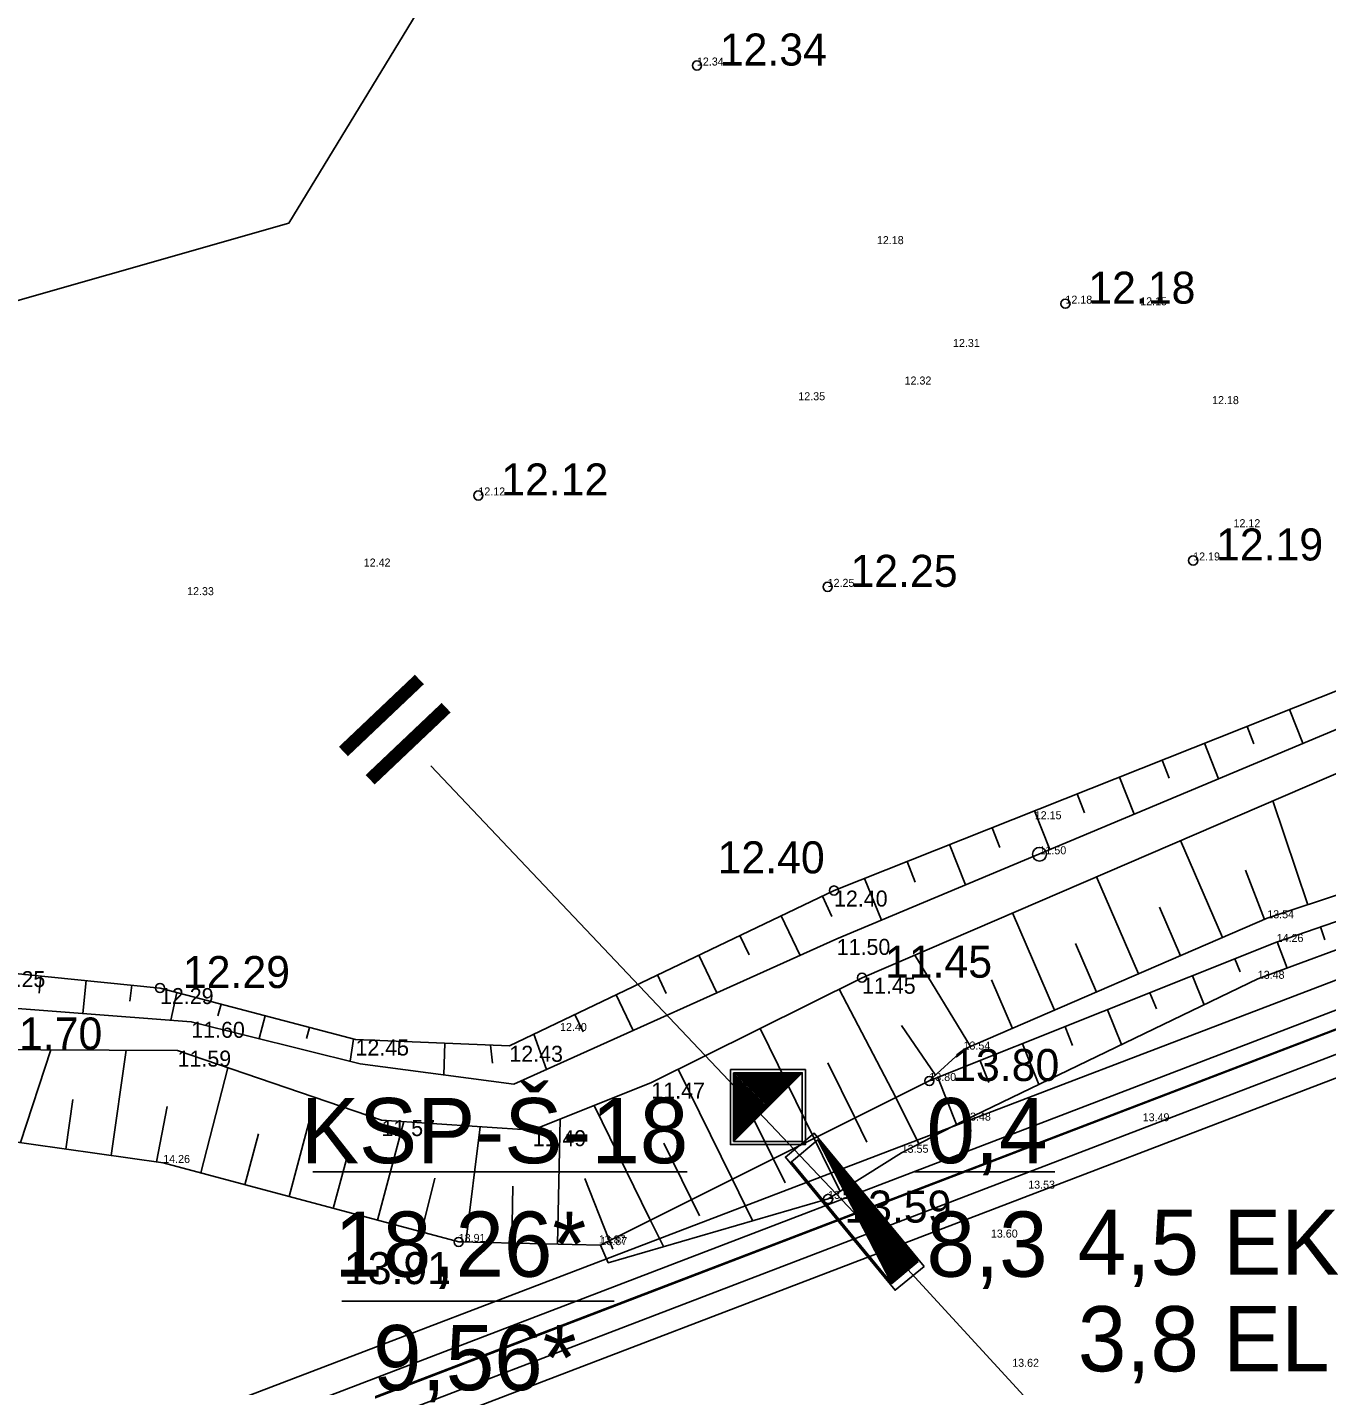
# Model space of a CAD drawing. Extents: x 433497 to 434382, y 6534486 to 6534993.
# Drawn here: x 433616.2 to 433673.1, y 6534797 to 6534856.4 of the extents above; entities that cross this region are included whole.
import ezdxf

# ---------------------------------------------------------------- set-up
doc = ezdxf.new("R2010")
doc.units = 0
for name, color, linetype in [('Default', 7, 'Continuous'), ('GEOLPUNKT', 7, 'Continuous'), ('kataster', 7, 'Continuous'), ('KORGUS-EH2000', 7, 'Continuous'), ('l__x00e4__bil__x00f5__iked', 7, 'Continuous'), ('MOOTKORG-EH2000', 7, 'Continuous'), ('PIIR', 7, 'Continuous'), ('RELJEEF', 7, 'Continuous'), ('VEEKOGU', 7, 'Continuous'), ('VORMISTUS', 7, 'Continuous')]:
    doc.layers.add(name, color=color, linetype=linetype)

msp = doc.modelspace()

# ---------------------------------------------------------------- linework, layer by layer
at = {"layer": 'Default'}
msp.add_lwpolyline([(433617.12, 6534791.025), (433632.75, 6534606.045), (434137.38, 6534796.515), (434127.69, 6534855.6), (433968.21, 6534911.925), (433942.38, 6534904.035), (433920.99, 6534907.275)], close=True, dxfattribs=at)
msp.add_lwpolyline([(433617.12, 6534791.025), (433632.75, 6534606.045), (434137.38, 6534796.515), (434127.69, 6534855.6), (433968.21, 6534911.925), (433942.38, 6534904.035), (433920.99, 6534907.275)], close=True, dxfattribs=at)
msp.add_lwpolyline([(433617.12, 6534791.025), (433632.75, 6534606.045), (434137.38, 6534796.515), (434127.69, 6534855.6), (433968.21, 6534911.925), (433942.38, 6534904.035), (433920.99, 6534907.275)], close=True, dxfattribs=at)
at = {"layer": 'GEOLPUNKT'}
for p, q in [((433647.136, 6534807.67), (433650.136, 6534810.67)), ((433647.136, 6534807.7), (433650.106, 6534810.67)), ((433647.136, 6534807.771), (433650.035, 6534810.67)), ((433647.136, 6534807.842), (433649.965, 6534810.67)), ((433647.136, 6534807.912), (433649.894, 6534810.67)), ((433647.136, 6534807.983), (433649.823, 6534810.67)), ((433647.136, 6534808.054), (433649.752, 6534810.67)), ((433647.136, 6534808.124), (433649.682, 6534810.67)), ((433647.136, 6534808.195), (433649.611, 6534810.67)), ((433647.136, 6534808.266), (433649.54, 6534810.67)), ((433647.136, 6534808.337), (433649.47, 6534810.67)), ((433647.136, 6534808.407), (433649.399, 6534810.67)), ((433647.136, 6534808.478), (433649.328, 6534810.67)), ((433647.136, 6534808.549), (433649.257, 6534810.67)), ((433647.136, 6534808.619), (433649.187, 6534810.67)), ((433647.136, 6534808.69), (433649.116, 6534810.67)), ((433647.136, 6534808.761), (433649.045, 6534810.67)), ((433647.136, 6534808.832), (433648.975, 6534810.67)), ((433647.136, 6534808.902), (433648.904, 6534810.67)), ((433647.136, 6534808.973), (433648.833, 6534810.67)), ((433647.136, 6534809.044), (433648.763, 6534810.67)), ((433647.136, 6534809.114), (433648.692, 6534810.67)), ((433647.136, 6534809.185), (433648.621, 6534810.67)), ((433647.136, 6534809.256), (433648.55, 6534810.67)), ((433647.136, 6534809.327), (433648.48, 6534810.67)), ((433647.136, 6534809.397), (433648.409, 6534810.67)), ((433647.136, 6534809.468), (433648.338, 6534810.67)), ((433647.136, 6534809.539), (433648.268, 6534810.67)), ((433647.136, 6534809.609), (433648.197, 6534810.67)), ((433647.136, 6534809.68), (433648.126, 6534810.67)), ((433647.136, 6534809.751), (433648.055, 6534810.67)), ((433647.136, 6534809.822), (433647.985, 6534810.67)), ((433647.136, 6534809.892), (433647.914, 6534810.67)), ((433647.136, 6534809.963), (433647.843, 6534810.67)), ((433647.136, 6534810.034), (433647.773, 6534810.67)), ((433647.136, 6534810.104), (433647.702, 6534810.67)), ((433647.136, 6534810.175), (433647.631, 6534810.67)), ((433647.136, 6534810.246), (433647.56, 6534810.67)), ((433647.136, 6534810.317), (433647.49, 6534810.67)), ((433647.136, 6534810.387), (433647.419, 6534810.67)), ((433647.136, 6534810.458), (433647.348, 6534810.67)), ((433647.136, 6534810.529), (433647.278, 6534810.67)), ((433647.136, 6534810.599), (433647.207, 6534810.67)), ((433648.636, 6534809.17), (433648.636, 6534809.17)), ((433650.818, 6534807.733), (433654.049, 6534801.455)), ((433650.863, 6534807.679), (433654.061, 6534801.465)), ((433650.966, 6534807.554), (433654.088, 6534801.487)), ((433651.069, 6534807.428), (433654.115, 6534801.51)), ((433651.173, 6534807.303), (433654.143, 6534801.532)), ((433651.276, 6534807.177), (433654.17, 6534801.555)), ((433651.38, 6534807.052), (433654.197, 6534801.577)), ((433651.483, 6534806.926), (433654.225, 6534801.6)), ((433651.587, 6534806.801), (433654.252, 6534801.622)), ((433651.69, 6534806.675), (433654.279, 6534801.645)), ((433651.794, 6534806.55), (433654.306, 6534801.667)), ((433651.897, 6534806.424), (433654.334, 6534801.69)), ((433652, 6534806.299), (433654.361, 6534801.712)), ((433652.104, 6534806.173), (433654.388, 6534801.734)), ((433652.207, 6534806.048), (433654.416, 6534801.757)), ((433652.311, 6534805.922), (433654.443, 6534801.779)), ((433652.414, 6534805.797), (433654.47, 6534801.802)), ((433652.518, 6534805.671), (433654.497, 6534801.824)), ((433652.621, 6534805.546), (433654.525, 6534801.847)), ((433652.724, 6534805.42), (433654.552, 6534801.869)), ((433652.828, 6534805.295), (433654.579, 6534801.892)), ((433652.931, 6534805.169), (433654.607, 6534801.914)), ((433653.035, 6534805.044), (433654.634, 6534801.937)), ((433653.138, 6534804.918), (433654.661, 6534801.959)), ((433653.242, 6534804.793), (433654.688, 6534801.982)), ((433653.345, 6534804.667), (433654.716, 6534802.004)), ((433653.449, 6534804.542), (433654.743, 6534802.027)), ((433653.552, 6534804.416), (433654.77, 6534802.049)), ((433653.655, 6534804.291), (433654.797, 6534802.072)), ((433653.759, 6534804.165), (433654.825, 6534802.094)), ((433653.862, 6534804.04), (433654.852, 6534802.117)), ((433653.966, 6534803.914), (433654.879, 6534802.139)), ((433654.069, 6534803.789), (433654.907, 6534802.162)), ((433654.173, 6534803.663), (433654.934, 6534802.184)), ((433654.276, 6534803.538), (433654.961, 6534802.207)), ((433654.38, 6534803.412), (433654.988, 6534802.229)), ((433654.483, 6534803.287), (433655.016, 6534802.252)), ((433654.586, 6534803.161), (433655.043, 6534802.274)), ((433654.69, 6534803.036), (433655.07, 6534802.297)), ((433654.793, 6534802.91), (433655.098, 6534802.319)), ((433654.897, 6534802.785), (433655.125, 6534802.342)), ((433655, 6534802.659), (433655.152, 6534802.364)), ((433655.104, 6534802.534), (433655.179, 6534802.387))]:
    msp.add_line(p, q, dxfattribs=at)
for points in [[(433646.995, 6534810.811), (433650.277, 6534810.811), (433650.277, 6534807.529), (433646.995, 6534807.529)], [(433647.136, 6534810.67), (433650.136, 6534810.67), (433650.136, 6534807.67), (433647.136, 6534807.67)], [(433655.467, 6534802.204), (433654.201, 6534801.16), (433649.4, 6534806.985), (433650.666, 6534808.029)], [(433655.207, 6534802.409), (433654.049, 6534801.455), (433649.66, 6534806.779), (433650.818, 6534807.733)]]:
    msp.add_lwpolyline(points, close=True, dxfattribs=at)
for points in [[(433628.724, 6534806.333), (433645.109, 6534806.333)], [(433655.06, 6534806.333), (433661.188, 6534806.333)], [(433629.995, 6534800.679), (433641.912, 6534800.679)]]:
    msp.add_lwpolyline(points, dxfattribs=at)
at = {"layer": 'kataster'}
msp.add_lwpolyline([(433617.102, 6534791.002), (433632.769, 6534606.029), (434137.446, 6534796.469), (434127.827, 6534855.589), (433950.026, 6534918.39)], close=True, dxfattribs=at)
at = {"layer": 'KORGUS-EH2000'}
for centre in [(433645.531, 6534854.725), (433661.65, 6534844.309), (433635.97, 6534835.92), (433667.238, 6534833.078), (433651.248, 6534831.924), (433651.528, 6534818.64), (433652.755, 6534814.828), (433622.045, 6534814.376), (433655.696, 6534810.311), (433651.269, 6534805.154), (433635.11, 6534803.273)]:
    msp.add_circle(centre, 0.2, dxfattribs=at)
at = {"layer": 'l__x00e4__bil__x00f5__iked'}
msp.add_lwpolyline([(433633.89, 6534824.093), (433654.744, 6534802.081), (433736.834, 6534712.709), (433742.792, 6534710.723), (433773.907, 6534661.568), (433785.989, 6534638.563)], dxfattribs=at)
at = {"layer": 'PIIR'}
for points in [[(433632.021, 6534604.835), (434138.248, 6534795.936), (434128.468, 6534856.135), (433968.226, 6534912.818), (433942.33, 6534904.85), (433920.952, 6534908.165), (433616.327, 6534791.524), (433632.021, 6534604.835)], [(433632.732, 6534605.959), (434137.353, 6534796.454), (434127.754, 6534855.539), (433968.208, 6534911.976), (433942.39, 6534904.031), (433921.04, 6534907.341), (433617.174, 6534790.992), (433632.732, 6534605.959)], [(433616.435, 6534792.923), (433775.118, 6534853.561)]]:
    msp.add_lwpolyline(points, dxfattribs=at)
for points in [[(433618.234, 6534790.327), (433921.149, 6534906.313), (433942.464, 6534903.008), (433968.187, 6534910.923), (434126.862, 6534854.794), (434136.235, 6534797.101), (433633.617, 6534607.362)], [(433619.24, 6534789.695), (433634.52, 6534608.851), (434135.141, 6534797.808), (434125.908, 6534854.108), (433968.165, 6534909.82), (433942.53, 6534901.99), (433921.212, 6534905.219)], [(433619.24, 6534789.695), (433634.52, 6534608.851), (434135.141, 6534797.808), (434125.908, 6534854.108), (433968.165, 6534909.82), (433942.53, 6534901.99), (433921.212, 6534905.219)]]:
    msp.add_lwpolyline(points, close=True, dxfattribs=at)
at = {"layer": 'RELJEEF'}
for p, q in [((433671.453, 6534826.557), (433672.039, 6534825.082)), ((433669.894, 6534825.063), (433669.594, 6534825.818)), ((433667.735, 6534825.08), (433668.349, 6534823.534)), ((433666.191, 6534823.55), (433665.877, 6534824.341)), ((433664.018, 6534823.603), (433664.66, 6534821.986)), ((433662.488, 6534822.038), (433662.159, 6534822.864)), ((433672.246, 6534818.016), (433670.722, 6534822.561)), ((433660.301, 6534822.126), (433660.971, 6534820.438)), ((433658.784, 6534820.525), (433658.442, 6534821.387)), ((433656.583, 6534820.649), (433657.282, 6534818.89)), ((433668.517, 6534816.581), (433666.683, 6534820.823)), ((433655.081, 6534819.013), (433654.725, 6534819.91)), ((433669.523, 6534819.531), (433670.353, 6534817.375)), ((433652.866, 6534819.172), (433653.61, 6534817.349)), ((433664.845, 6534814.994), (433663.009, 6534819.242)), ((433651.425, 6534817.5), (433651.022, 6534818.398)), ((433661.173, 6534813.407), (433659.335, 6534817.66)), ((433665.764, 6534817.91), (433666.681, 6534815.788)), ((433649.218, 6534817.536), (433650.046, 6534815.805)), ((433673, 6534816.492), (433672.808, 6534817.05)), ((433647.817, 6534815.829), (433647.414, 6534816.673)), ((433670.917, 6534816.399), (433671.343, 6534815.253)), ((433645.609, 6534815.81), (433646.397, 6534814.164)), ((433657.502, 6534811.82), (433655.062, 6534815.821)), ((433662.091, 6534816.326), (433663.009, 6534814.201)), ((433669.288, 6534815.087), (433669.06, 6534815.657)), ((433616.755, 6534814.158), (433616.83, 6534814.901)), ((433618.82, 6534814.701), (433618.675, 6534813.263)), ((433644.188, 6534814.145), (433643.805, 6534814.948)), ((433658.418, 6534814.742), (433659.338, 6534812.614)), ((433667.203, 6534814.914), (433667.711, 6534813.646)), ((433620.719, 6534813.807), (433620.81, 6534814.5)), ((433622.779, 6534814.183), (433622.522, 6534812.968)), ((433642, 6534814.085), (433642.748, 6534812.522)), ((433654.233, 6534809.592), (433651.749, 6534814.328)), ((433665.626, 6534813.473), (433665.346, 6534814.172)), ((433624.577, 6534813.159), (433624.713, 6534813.674)), ((433663.489, 6534813.429), (433664.1, 6534811.902)), ((433626.647, 6534813.165), (433626.383, 6534812.163)), ((433640.56, 6534812.462), (433640.196, 6534813.223)), ((433628.453, 6534812.169), (433628.581, 6534812.656)), ((433638.392, 6534812.36), (433638.95, 6534810.814)), ((433650.643, 6534807.828), (433648.294, 6534812.609)), ((433654.479, 6534812.745), (433655.968, 6534810.561)), ((433661.963, 6534811.858), (433661.632, 6534812.686)), ((433615.944, 6534807.614), (433617.266, 6534811.67)), ((433619.905, 6534807.05), (433620.559, 6534811.652)), ((433630.515, 6534812.147), (433630.365, 6534811.175)), ((433632.484, 6534811.448), (433632.511, 6534812.048)), ((433634.509, 6534811.966), (433634.453, 6534810.583)), ((433636.59, 6534811.086), (433636.508, 6534811.884)), ((433659.775, 6534811.943), (433660.489, 6534810.159)), ((433651.261, 6534811.105), (433652.438, 6534808.71)), ((433658.301, 6534810.243), (433657.918, 6534811.2)), ((433623.824, 6534806.288), (433625.009, 6534810.892)), ((433647.052, 6534806.065), (433644.713, 6534810.827)), ((433656.062, 6534810.457), (433656.882, 6534808.406)), ((433618.233, 6534809.498), (433617.925, 6534807.332)), ((433627.689, 6534805.256), (433628.845, 6534809.585)), ((433647.675, 6534809.332), (433648.847, 6534806.947)), ((433654.233, 6534809.592), (433655.233, 6534807.556)), ((433622.358, 6534809.201), (433621.885, 6534806.769)), ((433643.462, 6534804.301), (433641.036, 6534809.239)), ((433652.968, 6534807.631), (433652.438, 6534808.71)), ((433631.553, 6534804.223), (433632.706, 6534808.537)), ((433635.428, 6534803.266), (433636.052, 6534808.313)), ((433639.427, 6534803.176), (433639.551, 6534808.644)), ((433626.352, 6534808.002), (433625.756, 6534805.772)), ((433644.077, 6534807.585), (433645.257, 6534805.183)), ((433650.643, 6534807.828), (433651.794, 6534805.483)), ((433649.383, 6534805.856), (433648.847, 6534806.947)), ((433630.182, 6534806.839), (433629.621, 6534804.739)), ((433634.066, 6534806.057), (433633.485, 6534803.707)), ((433637.484, 6534805.717), (433637.428, 6534803.221)), ((433640.63, 6534806.04), (433641.667, 6534803.419)), ((433647.052, 6534806.065), (433647.967, 6534804.203)), ((433645.636, 6534804.412), (433645.257, 6534805.183)), ((433643.462, 6534804.301), (433644.063, 6534803.078)), ((433641.85, 6534802.957), (433641.667, 6534803.419))]:
    msp.add_line(p, q, dxfattribs=at)
for points in [[(433749.058, 6534856.332), (433741.841, 6534853.465), (433717.91, 6534845.411), (433702.328, 6534840.514), (433691.755, 6534835.121), (433679.525, 6534829.764), (433651.528, 6534818.64), (433637.327, 6534811.851), (433630.595, 6534812.126), (433622.045, 6534814.376), (433614.685, 6534815.117), (433605.841, 6534812.999), (433591.428, 6534809.544), (433575.413, 6534803.952), (433570.231, 6534802.507)], [(433641.312, 6534803.133), (433641.312, 6534803.133), (433655.696, 6534810.311), (433657.191, 6534811.686), (433670.478, 6534817.429), (433684.961, 6534822.24), (433699.73, 6534829.782), (433713.567, 6534836.247), (433729.115, 6534842.346), (433744.26, 6534848.225), (433749.491, 6534850.215), (433750.242, 6534848.987), (433750.768, 6534848.139), (433755.391, 6534846.995), (433755.787, 6534835.054), (433756.5, 6534822.235), (433759.761, 6534816.596), (433770.429, 6534806.118), (433779.564, 6534811.62), (433786.937, 6534803.288), (433796.573, 6534795.821), (433800.033, 6534788.924)], [(433655.696, 6534810.311), (433670.889, 6534816.389), (433685.476, 6534821.413), (433699.519, 6534828.41), (433714.557, 6534835.709), (433730.046, 6534840.914)], [(433730.566, 6534839.32), (433714.807, 6534834.556), (433700.329, 6534827.5), (433685.944, 6534820.634), (433670.062, 6534814.781), (433657.216, 6534808.578), (433654.486, 6534807.171), (433651.269, 6534805.154), (433641.651, 6534802.36), (433641.312, 6534803.133)], [(433641.312, 6534803.133), (433635.11, 6534803.273), (433622.185, 6534806.726), (433614.95, 6534807.755), (433613.943, 6534808.876), (433598.508, 6534805.623), (433588.385, 6534802.045), (433575.786, 6534796.741), (433561.572, 6534791.45), (433550.393, 6534787.427)]]:
    msp.add_lwpolyline(points, dxfattribs=at)
at = {"layer": 'VEEKOGU'}
for points in [[(433749.058, 6534856.332), (433741.841, 6534853.465), (433722.771, 6534845.253), (433710.509, 6534841.204), (433704.412, 6534838.967), (433698.912, 6534836.045), (433689.963, 6534831.852), (433681.025, 6534828.643), (433674.289, 6534826.026), (433651.647, 6534816.525), (433637.528, 6534810.175), (433630.797, 6534811.068), (433623.412, 6534812.9), (433613.311, 6534813.674), (433591.338, 6534808.449), (433572.407, 6534802.271)], [(433572.968, 6534800.411), (433591.847, 6534807.886), (433613.835, 6534811.689), (433622.814, 6534811.64), (433631.731, 6534808.602), (433638.345, 6534808.16), (433643.538, 6534810.243), (433652.755, 6534814.828), (433676.018, 6534824.841), (433679.31, 6534824.215), (433682.459, 6534827.262), (433690.574, 6534830.588), (433710.129, 6534839.081), (433723.05, 6534843.918), (433736.064, 6534848.408), (433747.792, 6534853.33), (433748.765, 6534853.283)]]:
    msp.add_lwpolyline(points, dxfattribs=at)
msp.add_circle((433660.515, 6534820.226), 0.3, dxfattribs=at)
at = {"layer": 'VORMISTUS'}
msp.add_lwpolyline([(433756.833, 6534894.348), (433691.203, 6534872.087), (433653.508, 6534864.187), (433636.546, 6534862.392), (433627.673, 6534847.824), (433564.128, 6534829.695), (433582.608, 6534768.478), (433587.883, 6534751.004), (433591.763, 6534747.472), (433594.096, 6534737.418), (433589.968, 6534732.121), (433592.57, 6534706.447), (433596.133, 6534671.303), (433599.93, 6534613.558), (433630.448, 6534534.937), (433664.149, 6534549.227), (433704.536, 6534572.568), (433752.081, 6534596.222), (433789.501, 6534614.839)], dxfattribs=at)
msp.add_lwpolyline([(433756.833, 6534894.348), (433691.203, 6534872.087), (433653.508, 6534864.187), (433636.546, 6534862.392), (433627.673, 6534847.824), (433564.128, 6534829.695), (433582.608, 6534768.478), (433587.883, 6534751.004), (433591.763, 6534747.472), (433594.096, 6534737.418), (433589.968, 6534732.121), (433592.57, 6534706.447), (433596.133, 6534671.303), (433599.93, 6534613.558), (433630.448, 6534534.937), (433664.149, 6534549.227), (433704.536, 6534572.568), (433752.081, 6534596.222), (433789.501, 6534614.839)], dxfattribs=at)

# ---------------------------------------------------------------- texts
at = {"layer": 'GEOLPUNKT'}
for s, p in [('KSP-Š-18', (433628.207, 6534806.715)), ('0,4', (433655.571, 6534806.715)), ('18,26*', (433629.671, 6534801.75)), ('8,3', (433655.571, 6534801.75)), ('4,5 EK', (433662.192, 6534801.833)), ('3,8 EL', (433662.192, 6534797.613)), ('9,56*', (433631.366, 6534796.785))]:
    msp.add_text(s, height=2.85, dxfattribs=at).set_placement(p)
at = {"layer": 'KORGUS-EH2000'}
for s, p in [('12.34', (433646.531, 6534854.725)), ('12.18', (433662.65, 6534844.309)), ('12.12', (433636.97, 6534835.92)), ('12.19', (433668.238, 6534833.078)), ('12.25', (433652.248, 6534831.924)), ('12.40', (433646.435, 6534819.394)), ('11.45', (433653.755, 6534814.828)), ('12.29', (433623.045, 6534814.376)), ('11.70', (433614.835, 6534811.689)), ('13.80', (433656.696, 6534810.311)), ('13.59', (433651.979, 6534804.118)), ('13.91', (433630.09, 6534801.427))]:
    msp.add_text(s, height=1.4, dxfattribs=at).set_placement(p)
at = {"layer": 'l__x00e4__bil__x00f5__iked'}
msp.add_text('II', height=4.58, rotation=313.47906, dxfattribs=at).set_placement((433629.481, 6534825.339))
at = {"layer": 'MOOTKORG-EH2000'}
for s, height, p in [('12.34', 0.35, (433645.531, 6534854.725)), ('12.18', 0.35, (433653.403, 6534846.913)), ('12.18', 0.35, (433661.65, 6534844.309)), ('12.15', 0.35, (433664.92, 6534844.239)), ('12.31', 0.35, (433656.731, 6534842.415)), ('12.32', 0.35, (433654.614, 6534840.773)), ('12.35', 0.35, (433649.965, 6534840.085)), ('12.18', 0.35, (433668.064, 6534839.916)), ('12.12', 0.35, (433635.97, 6534835.92)), ('12.12', 0.35, (433669.002, 6534834.533)), ('12.42', 0.35, (433630.956, 6534832.812)), ('12.19', 0.35, (433667.238, 6534833.078)), ('12.33', 0.35, (433623.23, 6534831.56)), ('12.25', 0.35, (433651.248, 6534831.924)), ('12.15', 0.35, (433660.308, 6534821.759)), ('11.50', 0.35, (433660.515, 6534820.226)), ('12.40', 0.7, (433651.528, 6534817.94)), ('13.54', 0.35, (433670.478, 6534817.429)), ('11.50', 0.7, (433651.647, 6534815.825)), ('14.26', 0.35, (433670.889, 6534816.389)), ('12.25', 0.7, (433614.685, 6534814.417)), ('11.45', 0.7, (433652.755, 6534814.128)), ('13.48', 0.35, (433670.062, 6534814.781)), ('12.29', 0.7, (433622.045, 6534813.676)), ('11.60', 0.7, (433623.412, 6534812.2)), ('12.40', 0.35, (433639.542, 6534812.499)), ('11.59', 0.7, (433622.814, 6534810.94)), ('12.45', 0.7, (433630.595, 6534811.426)), ('12.43', 0.7, (433637.327, 6534811.151)), ('13.54', 0.35, (433657.191, 6534811.686)), ('13.80', 0.35, (433655.696, 6534810.311)), ('11.47', 0.7, (433643.538, 6534809.543)), ('13.48', 0.35, (433657.216, 6534808.578)), ('13.49', 0.35, (433665.029, 6534808.55)), ('11.57', 0.7, (433631.731, 6534807.902)), ('11.49', 0.7, (433638.345, 6534807.46)), ('13.55', 0.35, (433654.486, 6534807.171)), ('14.26', 0.35, (433622.185, 6534806.726)), ('13.53', 0.35, (433660.021, 6534805.602)), ('13.59', 0.35, (433651.269, 6534805.154)), ('13.91', 0.35, (433635.11, 6534803.273)), ('13.87', 0.35, (433641.239, 6534803.209)), ('13.87', 0.35, (433641.312, 6534803.133)), ('13.60', 0.35, (433658.39, 6534803.462)), ('13.62', 0.35, (433659.322, 6534797.81))]:
    msp.add_text(s, height=height, dxfattribs=at).set_placement(p)

doc.saveas('drawing.dxf')
